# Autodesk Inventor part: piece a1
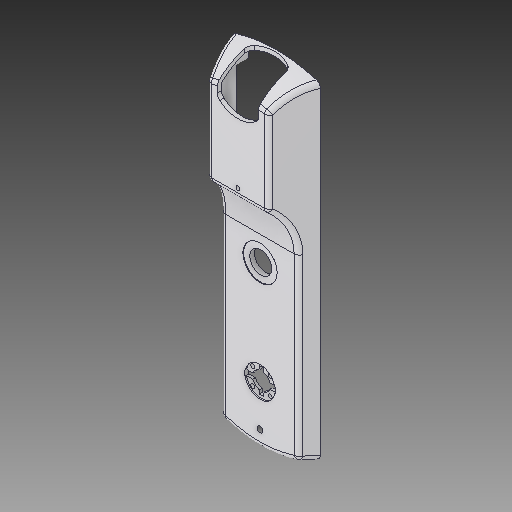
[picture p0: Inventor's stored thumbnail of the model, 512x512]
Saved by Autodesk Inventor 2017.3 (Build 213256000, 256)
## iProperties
Created: 2002-03
Part Number: piece a1
Material: solidworks materials|Alliage 7079|22
Document SubType Name: Modeling
Designer: ficho
Density: 2.7 g/cm^3
Appearance: 227,227,2331
Author: ficho
Sending System: SolidWorks 2009
Last Author: christophe
Last Saved: 2011-02-10
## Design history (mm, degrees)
feature "Trou taraudé M33"
node "Solide1"
